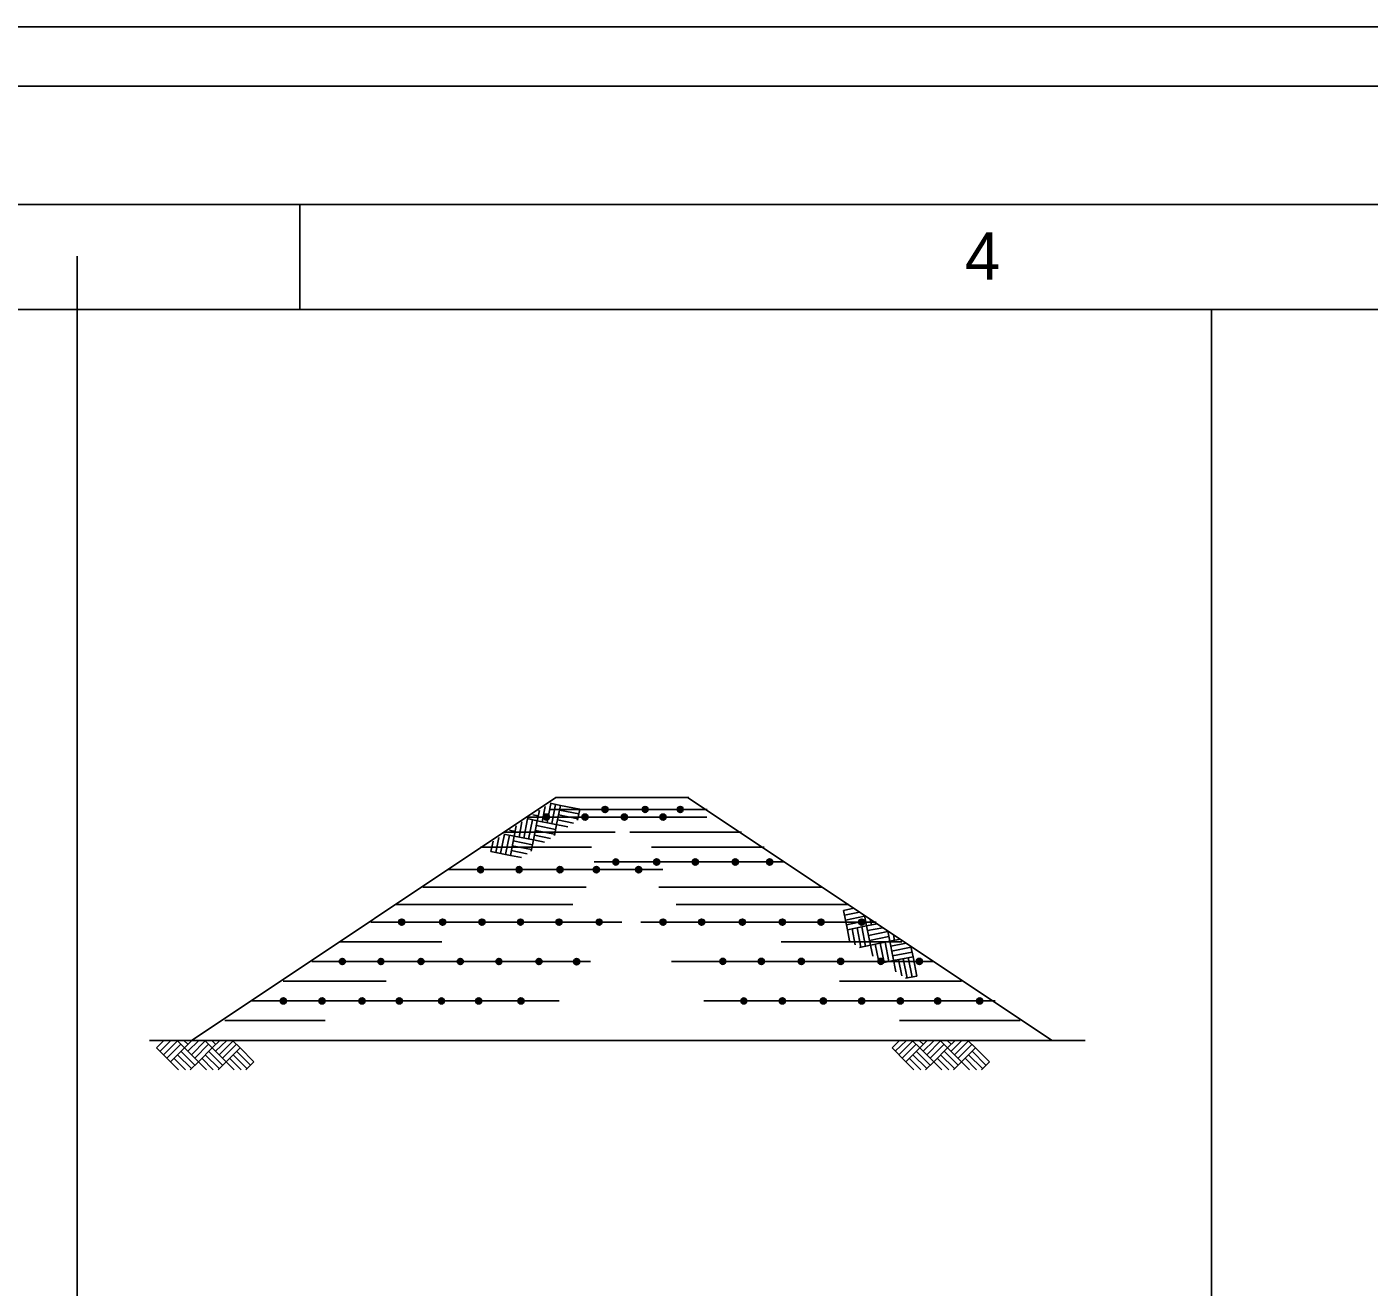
# Model space of a CAD drawing. Extents: x -0.04 to 2.79, y -0.02 to 1.81.
# Drawn here: x 0.5018 to 0.9741, y 1.369 to 1.8125 of the extents above; entities that cross this region are included whole.
import ezdxf

# ---------------------------------------------------------------- set-up
doc = ezdxf.new("R2010")
doc.units = 0
for name, color, linetype in [('G-ANNO-NPLT', 7, 'Continuous'), ('G-ANNO-PLOT', 7, 'Continuous'), ('G-ANNO-TTLB', 7, 'Continuous'), ('Level 1', 7, 'Continuous')]:
    doc.layers.add(name, color=color, linetype=linetype)

msp = doc.modelspace()

# ---------------------------------------------------------------- linework, layer by layer
for p, q in [((0.51951, 1.73185), (0.51951, 0.08028)), ((0.91867, 1.71305), (0.91867, 0.08028))]:
    msp.add_line(p, q)
at = {"layer": 'G-ANNO-NPLT'}
msp.add_lwpolyline([(-0.04167, 1.8125), (2.79167, 1.8125), (2.79167, -0.02083), (-0.04167, -0.02083)], close=True, dxfattribs=at)
at = {"layer": 'G-ANNO-PLOT'}
msp.add_line((2.79167, 1.8125), (-0.04167, 1.8125), dxfattribs=at)
msp.add_lwpolyline([(0, 0), (2.79167, 0), (2.79167, 1.79167), (0, 1.79167)], close=True, dxfattribs=at)
at = {"layer": 'G-ANNO-TTLB'}
msp.add_line((0.59784, 1.71305), (0.59784, 1.75), dxfattribs=at)
for points in [[(0.08333, 0.04167), (2.72917, 0.04167), (2.72917, 1.75), (0.2515, 1.75)], [(0.11656, 0.08028), (2.69501, 0.08028), (2.69501, 1.71305), (0.11656, 1.71305)]]:
    msp.add_lwpolyline(points, dxfattribs=at)
at = {"layer": 'Level 1'}
for p, q in [((0.68796, 1.54137), (0.55994, 1.45594)), ((0.73471, 1.54137), (0.68796, 1.54137)), ((0.73423, 1.54137), (0.86253, 1.4558)), ((0.68174, 1.53488), (0.67976, 1.53522)), ((0.6814, 1.53317), (0.68215, 1.53679)), ((0.6814, 1.53317), (0.68215, 1.53679)), ((0.68208, 1.53659), (0.68181, 1.53659)), ((0.68311, 1.53283), (0.68413, 1.53816)), ((0.68482, 1.53249), (0.68611, 1.53926)), ((0.68953, 1.53857), (0.68591, 1.53932)), ((0.74121, 1.53714), (0.68605, 1.53714)), ((0.68646, 1.53215), (0.68782, 1.53891)), ((0.68817, 1.53181), (0.68953, 1.53857)), ((0.69568, 1.53386), (0.68885, 1.53522)), ((0.69603, 1.53556), (0.68919, 1.53693)), ((0.69637, 1.53727), (0.68953, 1.53857)), ((0.69555, 1.53331), (0.69637, 1.53727)), ((0.67326, 1.5277), (0.67395, 1.53139)), ((0.67326, 1.5277), (0.67395, 1.53139)), ((0.67395, 1.53112), (0.67368, 1.53119)), ((0.67497, 1.52736), (0.676, 1.53276)), ((0.67661, 1.52702), (0.67798, 1.53386)), ((0.6814, 1.53317), (0.67778, 1.53392)), ((0.74107, 1.53447), (0.67791, 1.53447)), ((0.67832, 1.52668), (0.67969, 1.53351)), ((0.68003, 1.52641), (0.6814, 1.53317)), ((0.68782, 1.5301), (0.68106, 1.53146)), ((0.69213, 1.53105), (0.6814, 1.53317)), ((0.68741, 1.52791), (0.68817, 1.53181)), ((0.69418, 1.53235), (0.68851, 1.53351)), ((0.66506, 1.5223), (0.66581, 1.52593)), ((0.66677, 1.52196), (0.66787, 1.52729)), ((0.66848, 1.52162), (0.66985, 1.52839)), ((0.70874, 1.52914), (0.66951, 1.52914)), ((0.67326, 1.5277), (0.66957, 1.52846)), ((0.67019, 1.52128), (0.67156, 1.52805)), ((0.67361, 1.52941), (0.67162, 1.52982)), ((0.6719, 1.52094), (0.67326, 1.5277)), ((0.67969, 1.5247), (0.67292, 1.52606)), ((0.68003, 1.52641), (0.67326, 1.5277)), ((0.67928, 1.52244), (0.68003, 1.52641)), ((0.68393, 1.52559), (0.68003, 1.52641)), ((0.68598, 1.52695), (0.68037, 1.52805)), ((0.68748, 1.52839), (0.68072, 1.52975)), ((0.7533, 1.52914), (0.714, 1.52914)), ((0.70047, 1.52388), (0.66144, 1.52388)), ((0.6719, 1.52094), (0.66506, 1.5223)), ((0.67579, 1.52019), (0.6719, 1.52094)), ((0.67784, 1.52148), (0.67224, 1.52265)), ((0.67935, 1.52299), (0.67258, 1.52435)), ((0.76116, 1.52388), (0.72159, 1.52388)), ((0.7682, 1.51868), (0.70136, 1.51868)), ((0.72555, 1.51595), (0.64989, 1.51595)), ((0.69855, 1.5098), (0.64114, 1.5098)), ((0.7814, 1.5098), (0.72412, 1.5098)), ((0.69391, 1.50364), (0.63171, 1.50364)), ((0.79103, 1.50364), (0.7302, 1.50364)), ((0.78912, 1.50159), (0.79274, 1.50235)), ((0.71113, 1.49749), (0.62282, 1.49749)), ((0.8006, 1.49749), (0.71783, 1.49749)), ((0.79049, 1.49483), (0.78912, 1.50159)), ((0.78946, 1.49989), (0.79479, 1.50098)), ((0.7898, 1.49818), (0.79657, 1.49954)), ((0.79014, 1.49654), (0.79691, 1.4979)), ((0.79725, 1.49619), (0.79657, 1.49982)), ((0.79896, 1.49654), (0.79855, 1.49845)), ((0.79049, 1.49483), (0.79725, 1.49619)), ((0.79124, 1.49086), (0.79049, 1.49483)), ((0.79329, 1.4895), (0.7922, 1.49517)), ((0.7952, 1.48868), (0.7939, 1.49551)), ((0.79691, 1.48902), (0.79554, 1.49585)), ((0.79725, 1.49619), (0.80094, 1.49688)), ((0.79725, 1.49619), (0.80094, 1.49688)), ((0.79862, 1.48936), (0.79725, 1.49619)), ((0.7976, 1.49449), (0.80293, 1.49551)), ((0.79794, 1.49278), (0.80477, 1.49414)), ((0.80067, 1.49688), (0.8006, 1.49708)), ((0.80546, 1.49073), (0.8047, 1.49435)), ((0.8071, 1.49107), (0.80675, 1.49305)), ((0.64784, 1.49059), (0.61168, 1.49059)), ((0.80969, 1.49059), (0.76718, 1.49059)), ((0.79472, 1.48861), (0.79862, 1.48936)), ((0.79828, 1.49107), (0.80511, 1.49243)), ((0.79862, 1.48936), (0.80546, 1.49073)), ((0.79944, 1.48546), (0.79862, 1.48936)), ((0.80142, 1.4841), (0.80033, 1.4897)), ((0.8034, 1.48328), (0.80204, 1.49004)), ((0.80511, 1.48362), (0.80375, 1.49038)), ((0.80546, 1.49073), (0.80908, 1.49148)), ((0.80546, 1.49073), (0.80908, 1.49148)), ((0.80757, 1.48), (0.80546, 1.49073)), ((0.8058, 1.48902), (0.81113, 1.49011)), ((0.80607, 1.48731), (0.81291, 1.48868)), ((0.8088, 1.49141), (0.8088, 1.49168)), ((0.81359, 1.48533), (0.81284, 1.48895)), ((0.70006, 1.48362), (0.60211, 1.48362)), ((0.82097, 1.48362), (0.72856, 1.48362)), ((0.80286, 1.48314), (0.80675, 1.48396)), ((0.80641, 1.48567), (0.81325, 1.48697)), ((0.80675, 1.48396), (0.81359, 1.48533)), ((0.80962, 1.47863), (0.80846, 1.4843)), ((0.81154, 1.47781), (0.81017, 1.48464)), ((0.81325, 1.47815), (0.81188, 1.48498)), ((0.81496, 1.47849), (0.81359, 1.48533)), ((0.81099, 1.47774), (0.81496, 1.47849)), ((0.62822, 1.47671), (0.592, 1.47671)), ((0.83068, 1.47671), (0.78775, 1.47671)), ((0.68905, 1.46974), (0.58072, 1.46974)), ((0.8425, 1.46974), (0.73998, 1.46974)), ((0.60676, 1.46284), (0.57142, 1.46284)), ((0.85125, 1.46284), (0.8088, 1.46284)), ((0.87415, 1.45587), (0.54497, 1.45587)), ((0.54743, 1.45327), (0.55003, 1.45587)), ((0.54866, 1.45204), (0.55249, 1.45587)), ((0.54982, 1.45081), (0.55474, 1.45573)), ((0.55721, 1.45327), (0.55461, 1.45587)), ((0.55844, 1.4545), (0.557, 1.45587)), ((0.55721, 1.45327), (0.5598, 1.45587)), ((0.55721, 1.45327), (0.5598, 1.45587)), ((0.55844, 1.45204), (0.56226, 1.45587)), ((0.55967, 1.45573), (0.55946, 1.45587)), ((0.55967, 1.45081), (0.56452, 1.45573)), ((0.56698, 1.45327), (0.56438, 1.45587)), ((0.56821, 1.4545), (0.56684, 1.45587)), ((0.56698, 1.45327), (0.56965, 1.45587)), ((0.56698, 1.45327), (0.56965, 1.45587)), ((0.56821, 1.45204), (0.57211, 1.45587)), ((0.56944, 1.45573), (0.56924, 1.45587)), ((0.56944, 1.45081), (0.57436, 1.45573)), ((0.57682, 1.45327), (0.57416, 1.45587)), ((0.80621, 1.45327), (0.8088, 1.45587)), ((0.80737, 1.45204), (0.81127, 1.45587)), ((0.8086, 1.45081), (0.81352, 1.45573)), ((0.81598, 1.45327), (0.81332, 1.45587)), ((0.81721, 1.4545), (0.81578, 1.45587)), ((0.81598, 1.45327), (0.81858, 1.45587)), ((0.81598, 1.45327), (0.81858, 1.45587)), ((0.81721, 1.45204), (0.82104, 1.45587)), ((0.81844, 1.45573), (0.81824, 1.45587)), ((0.81844, 1.45081), (0.8233, 1.45573)), ((0.82576, 1.45327), (0.82316, 1.45587)), ((0.82699, 1.4545), (0.82562, 1.45587)), ((0.82576, 1.45327), (0.82842, 1.45587)), ((0.82576, 1.45327), (0.82842, 1.45587)), ((0.82699, 1.45204), (0.83081, 1.45587)), ((0.82822, 1.45573), (0.82801, 1.45587)), ((0.82822, 1.45081), (0.83314, 1.45573)), ((0.8356, 1.45327), (0.83293, 1.45587)), ((0.55228, 1.44835), (0.54743, 1.45327)), ((0.55105, 1.44958), (0.55597, 1.4545)), ((0.55228, 1.44835), (0.55721, 1.45327)), ((0.55967, 1.44596), (0.55474, 1.45081)), ((0.5609, 1.44712), (0.55597, 1.45204)), ((0.56213, 1.44835), (0.55721, 1.45327)), ((0.5609, 1.44958), (0.56575, 1.4545)), ((0.56213, 1.44835), (0.56698, 1.45327)), ((0.56944, 1.44596), (0.56452, 1.45081)), ((0.57067, 1.44712), (0.56575, 1.45204)), ((0.5747, 1.44555), (0.56698, 1.45327)), ((0.57067, 1.44958), (0.57559, 1.4545)), ((0.5719, 1.44835), (0.57682, 1.45327)), ((0.57921, 1.44596), (0.57436, 1.45081)), ((0.58044, 1.44712), (0.57559, 1.45204)), ((0.58167, 1.44835), (0.57682, 1.45327)), ((0.81106, 1.44835), (0.80621, 1.45327)), ((0.80983, 1.44958), (0.81475, 1.4545)), ((0.81106, 1.44835), (0.81598, 1.45327)), ((0.81844, 1.44596), (0.81352, 1.45081)), ((0.81967, 1.44712), (0.81475, 1.45204)), ((0.8209, 1.44835), (0.81598, 1.45327)), ((0.81967, 1.44958), (0.82453, 1.4545)), ((0.8209, 1.44835), (0.82576, 1.45327)), ((0.82822, 1.44596), (0.8233, 1.45081)), ((0.82945, 1.44712), (0.82453, 1.45204)), ((0.83348, 1.44555), (0.82576, 1.45327)), ((0.82945, 1.44958), (0.83437, 1.4545)), ((0.83068, 1.44835), (0.8356, 1.45327)), ((0.83799, 1.44596), (0.83314, 1.45081)), ((0.83922, 1.44712), (0.83437, 1.45204)), ((0.84045, 1.44835), (0.8356, 1.45327)), ((0.55515, 1.44555), (0.55228, 1.44835)), ((0.55762, 1.44555), (0.55351, 1.44958)), ((0.55926, 1.44555), (0.56213, 1.44835)), ((0.56493, 1.44555), (0.56213, 1.44835)), ((0.56739, 1.44555), (0.56336, 1.44958)), ((0.5691, 1.44555), (0.5719, 1.44835)), ((0.57716, 1.44555), (0.57313, 1.44958)), ((0.57887, 1.44555), (0.58167, 1.44835)), ((0.81393, 1.44555), (0.81106, 1.44835)), ((0.81639, 1.44555), (0.81229, 1.44958)), ((0.81803, 1.44555), (0.8209, 1.44835)), ((0.82371, 1.44555), (0.8209, 1.44835)), ((0.82617, 1.44555), (0.82206, 1.44958)), ((0.82787, 1.44555), (0.83068, 1.44835)), ((0.83594, 1.44555), (0.83191, 1.44958)), ((0.83765, 1.44555), (0.84045, 1.44835))]:
    msp.add_line(p, q, dxfattribs=at)
for centre, radius in [((0.68462, 1.53443), 0.00107), ((0.68462, 1.53443), 0.000828), ((0.6982, 1.53443), 0.00107), ((0.6982, 1.53443), 0.000828), ((0.70525, 1.53712), 0.00107), ((0.70525, 1.53712), 0.000828), ((0.70525, 1.53712), 0.000607), ((0.70525, 1.53712), 0.000307), ((0.71204, 1.53443), 0.00107), ((0.71204, 1.53443), 0.000828), ((0.71934, 1.53712), 0.00107), ((0.71934, 1.53712), 0.000828), ((0.71934, 1.53712), 0.000607), ((0.71934, 1.53712), 0.000307), ((0.72563, 1.53443), 0.00107), ((0.72563, 1.53443), 0.000828), ((0.73167, 1.53712), 0.00107), ((0.73167, 1.53712), 0.000828), ((0.73167, 1.53712), 0.000607), ((0.73167, 1.53712), 0.000307), ((0.68462, 1.53443), 0.000607), ((0.68462, 1.53443), 0.000307), ((0.6982, 1.53443), 0.000607), ((0.6982, 1.53443), 0.000307), ((0.71204, 1.53443), 0.000607), ((0.71204, 1.53443), 0.000307), ((0.72563, 1.53443), 0.000607), ((0.72563, 1.53443), 0.000307), ((0.66141, 1.51595), 0.00107), ((0.66141, 1.51595), 0.000828), ((0.66141, 1.51595), 0.000607), ((0.66141, 1.51595), 0.000307), ((0.675, 1.51595), 0.00107), ((0.675, 1.51595), 0.000828), ((0.675, 1.51595), 0.000607), ((0.675, 1.51595), 0.000307), ((0.68934, 1.51595), 0.00107), ((0.68934, 1.51595), 0.000828), ((0.68934, 1.51595), 0.000607), ((0.68934, 1.51595), 0.000307), ((0.70218, 1.51595), 0.00107), ((0.70218, 1.51595), 0.000828), ((0.70218, 1.51595), 0.000607), ((0.70218, 1.51595), 0.000307), ((0.70902, 1.51865), 0.00107), ((0.70902, 1.51865), 0.000828), ((0.70902, 1.51865), 0.000607), ((0.70902, 1.51865), 0.000307), ((0.71702, 1.51595), 0.00107), ((0.71702, 1.51595), 0.000828), ((0.71702, 1.51595), 0.000607), ((0.71702, 1.51595), 0.000307), ((0.72336, 1.51865), 0.00107), ((0.72336, 1.51865), 0.000828), ((0.72336, 1.51865), 0.000607), ((0.72336, 1.51865), 0.000307), ((0.73695, 1.51865), 0.00107), ((0.73695, 1.51865), 0.000828), ((0.73695, 1.51865), 0.000607), ((0.73695, 1.51865), 0.000307), ((0.75104, 1.51865), 0.00107), ((0.75104, 1.51865), 0.000828), ((0.75104, 1.51865), 0.000607), ((0.75104, 1.51865), 0.000307), ((0.76312, 1.51865), 0.00107), ((0.76312, 1.51865), 0.000828), ((0.76312, 1.51865), 0.000607), ((0.76312, 1.51865), 0.000307), ((0.63371, 1.49748), 0.00107), ((0.63371, 1.49748), 0.000828), ((0.63371, 1.49748), 0.000607), ((0.63371, 1.49748), 0.000307), ((0.64805, 1.49748), 0.00107), ((0.64805, 1.49748), 0.000828), ((0.64805, 1.49748), 0.000607), ((0.64805, 1.49748), 0.000307), ((0.66189, 1.49748), 0.00107), ((0.66189, 1.49748), 0.000828), ((0.66189, 1.49748), 0.000607), ((0.66189, 1.49748), 0.000307), ((0.67548, 1.49748), 0.00107), ((0.67548, 1.49748), 0.000828), ((0.67548, 1.49748), 0.000607), ((0.67548, 1.49748), 0.000307), ((0.68907, 1.49748), 0.00107), ((0.68907, 1.49748), 0.000828), ((0.68907, 1.49748), 0.000607), ((0.68907, 1.49748), 0.000307), ((0.70316, 1.49748), 0.00107), ((0.70316, 1.49748), 0.000828), ((0.70316, 1.49748), 0.000607), ((0.70316, 1.49748), 0.000307), ((0.72563, 1.49748), 0.00107), ((0.72563, 1.49748), 0.000828), ((0.72563, 1.49748), 0.000607), ((0.72563, 1.49748), 0.000307), ((0.73921, 1.49748), 0.00107), ((0.73921, 1.49748), 0.000828), ((0.73921, 1.49748), 0.000607), ((0.73921, 1.49748), 0.000307), ((0.75356, 1.49748), 0.00107), ((0.75356, 1.49748), 0.000828), ((0.75356, 1.49748), 0.000607), ((0.75356, 1.49748), 0.000307), ((0.76765, 1.49748), 0.00107), ((0.76765, 1.49748), 0.000828), ((0.76765, 1.49748), 0.000607), ((0.76765, 1.49748), 0.000307), ((0.78123, 1.49748), 0.00107), ((0.78123, 1.49748), 0.000828), ((0.78123, 1.49748), 0.000607), ((0.78123, 1.49748), 0.000307), ((0.79557, 1.49748), 0.00107), ((0.79557, 1.49748), 0.000828), ((0.79557, 1.49748), 0.000607), ((0.79557, 1.49748), 0.000307), ((0.61276, 1.48363), 0.00107), ((0.61276, 1.48363), 0.000828), ((0.61276, 1.48363), 0.000607), ((0.61276, 1.48363), 0.000307), ((0.62634, 1.48363), 0.00107), ((0.62634, 1.48363), 0.000828), ((0.62634, 1.48363), 0.000607), ((0.62634, 1.48363), 0.000307), ((0.64043, 1.48363), 0.00107), ((0.64043, 1.48363), 0.000828), ((0.64043, 1.48363), 0.000607), ((0.64043, 1.48363), 0.000307), ((0.65427, 1.48363), 0.00107), ((0.65427, 1.48363), 0.000828), ((0.65427, 1.48363), 0.000607), ((0.65427, 1.48363), 0.000307), ((0.66786, 1.48363), 0.00107), ((0.66786, 1.48363), 0.000828), ((0.66786, 1.48363), 0.000607), ((0.66786, 1.48363), 0.000307), ((0.68195, 1.48363), 0.00107), ((0.68195, 1.48363), 0.000828), ((0.68195, 1.48363), 0.000607), ((0.68195, 1.48363), 0.000307), ((0.69521, 1.48356), 0.00107), ((0.69521, 1.48356), 0.000828), ((0.69521, 1.48356), 0.000607), ((0.69521, 1.48356), 0.000307), ((0.74667, 1.48366), 0.00107), ((0.74667, 1.48366), 0.000828), ((0.74667, 1.48366), 0.000607), ((0.74667, 1.48366), 0.000307), ((0.76025, 1.48366), 0.00107), ((0.76025, 1.48366), 0.000828), ((0.76025, 1.48366), 0.000607), ((0.76025, 1.48366), 0.000307), ((0.77434, 1.48366), 0.00107), ((0.77434, 1.48366), 0.000828), ((0.77434, 1.48366), 0.000607), ((0.77434, 1.48366), 0.000307), ((0.78818, 1.48366), 0.00107), ((0.78818, 1.48366), 0.000828), ((0.78818, 1.48366), 0.000607), ((0.78818, 1.48366), 0.000307), ((0.80227, 1.48366), 0.00107), ((0.80227, 1.48366), 0.000828), ((0.80227, 1.48366), 0.000607), ((0.80227, 1.48366), 0.000307), ((0.81586, 1.48366), 0.00107), ((0.81586, 1.48366), 0.000828), ((0.81586, 1.48366), 0.000607), ((0.81586, 1.48366), 0.000307), ((0.59207, 1.46977), 0.00107), ((0.59207, 1.46977), 0.000828), ((0.59207, 1.46977), 0.000607), ((0.59207, 1.46977), 0.000307), ((0.60566, 1.46977), 0.00107), ((0.60566, 1.46977), 0.000828), ((0.60566, 1.46977), 0.000607), ((0.60566, 1.46977), 0.000307), ((0.61975, 1.46977), 0.00107), ((0.61975, 1.46977), 0.000828), ((0.61975, 1.46977), 0.000607), ((0.61975, 1.46977), 0.000307), ((0.63283, 1.46977), 0.00107), ((0.63283, 1.46977), 0.000828), ((0.63283, 1.46977), 0.000607), ((0.63283, 1.46977), 0.000307), ((0.64768, 1.46977), 0.00107), ((0.64768, 1.46977), 0.000828), ((0.64768, 1.46977), 0.000607), ((0.64768, 1.46977), 0.000307), ((0.66076, 1.46977), 0.00107), ((0.66076, 1.46977), 0.000828), ((0.66076, 1.46977), 0.000607), ((0.66076, 1.46977), 0.000307), ((0.67561, 1.46977), 0.00107), ((0.67561, 1.46977), 0.000828), ((0.67561, 1.46977), 0.000607), ((0.67561, 1.46977), 0.000307), ((0.75406, 1.46977), 0.00107), ((0.75406, 1.46977), 0.000828), ((0.75406, 1.46977), 0.000607), ((0.75406, 1.46977), 0.000307), ((0.76765, 1.46977), 0.00107), ((0.76765, 1.46977), 0.000828), ((0.76765, 1.46977), 0.000607), ((0.76765, 1.46977), 0.000307), ((0.78199, 1.46977), 0.00107), ((0.78199, 1.46977), 0.000828), ((0.78199, 1.46977), 0.000607), ((0.78199, 1.46977), 0.000307), ((0.79557, 1.46977), 0.00107), ((0.79557, 1.46977), 0.000828), ((0.79557, 1.46977), 0.000607), ((0.79557, 1.46977), 0.000307), ((0.80916, 1.46977), 0.00107), ((0.80916, 1.46977), 0.000828), ((0.80916, 1.46977), 0.000607), ((0.80916, 1.46977), 0.000307), ((0.82225, 1.46977), 0.00107), ((0.82225, 1.46977), 0.000828), ((0.82225, 1.46977), 0.000607), ((0.82225, 1.46977), 0.000307), ((0.83709, 1.46977), 0.00107), ((0.83709, 1.46977), 0.000828), ((0.83709, 1.46977), 0.000607), ((0.83709, 1.46977), 0.000307)]:
    msp.add_circle(centre, radius, dxfattribs=at)

# ---------------------------------------------------------------- texts
at = {"layer": 'G-ANNO-TTLB'}
msp.add_text('4', height=0.01667, dxfattribs=at).set_placement((0.83187, 1.72352))

doc.saveas('drawing.dxf')
